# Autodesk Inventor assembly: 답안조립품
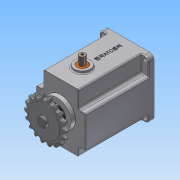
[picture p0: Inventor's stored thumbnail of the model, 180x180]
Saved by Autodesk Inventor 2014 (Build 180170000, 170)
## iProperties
Created: 2016-05
Part Number: 답안조립품
Document SubType Name: Assembly
Designer: 703-04
Mass: 2678.89 g
Surface Area: 1920.97 cm^2
Volume: 706.636 cm^3
Density: 3.79105 g/cm^3
Author: 703-04
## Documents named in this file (16)
- C:\Users\703-04\Desktop\360508V1007\답안조립품.iam
- C:\Users\703-04\Desktop\360508V1007\본체.ipt
- C:\Users\703-04\Desktop\360508V1007\커버.ipt
- C:\Users\703-04\Desktop\360508V1007\서브축.ipt
- C:\Users\703-04\Desktop\360508V1007\오일실 8 22 7.ipt
- C:\Users\703-04\Desktop\360508V1007\오일실 17 32 8.ipt
- C:\Users\703-04\Desktop\360508V1007\베어링 608.ipt
- C:\Users\703-04\Desktop\360508V1007\베어링 6003.ipt
- C:\Users\703-04\Desktop\360508V1007\메인축.ipt
- C:\Users\703-04\Desktop\360508V1007\키 5 x 5 x 18.ipt
- C:\Users\703-04\Desktop\360508V1007\가변 스프링.ipt
- C:\Users\703-04\Desktop\360508V1007\볼트 M4 x 10.ipt
- C:\Users\703-04\Desktop\360508V1007\부시.ipt
- C:\Users\703-04\Desktop\360508V1007\스프로킷.ipt
- C:\Users\703-04\Desktop\360508V1007\슬라이더.ipt
- C:\Users\703-04\Desktop\360508V1007\멈춤나사 M3x8.ipt
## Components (3 placed, 2 different names)
1. 가변 스프링:1
2. ISO 4762 M4 x 10:1
3. ISO 4762 M4 x 10:2
